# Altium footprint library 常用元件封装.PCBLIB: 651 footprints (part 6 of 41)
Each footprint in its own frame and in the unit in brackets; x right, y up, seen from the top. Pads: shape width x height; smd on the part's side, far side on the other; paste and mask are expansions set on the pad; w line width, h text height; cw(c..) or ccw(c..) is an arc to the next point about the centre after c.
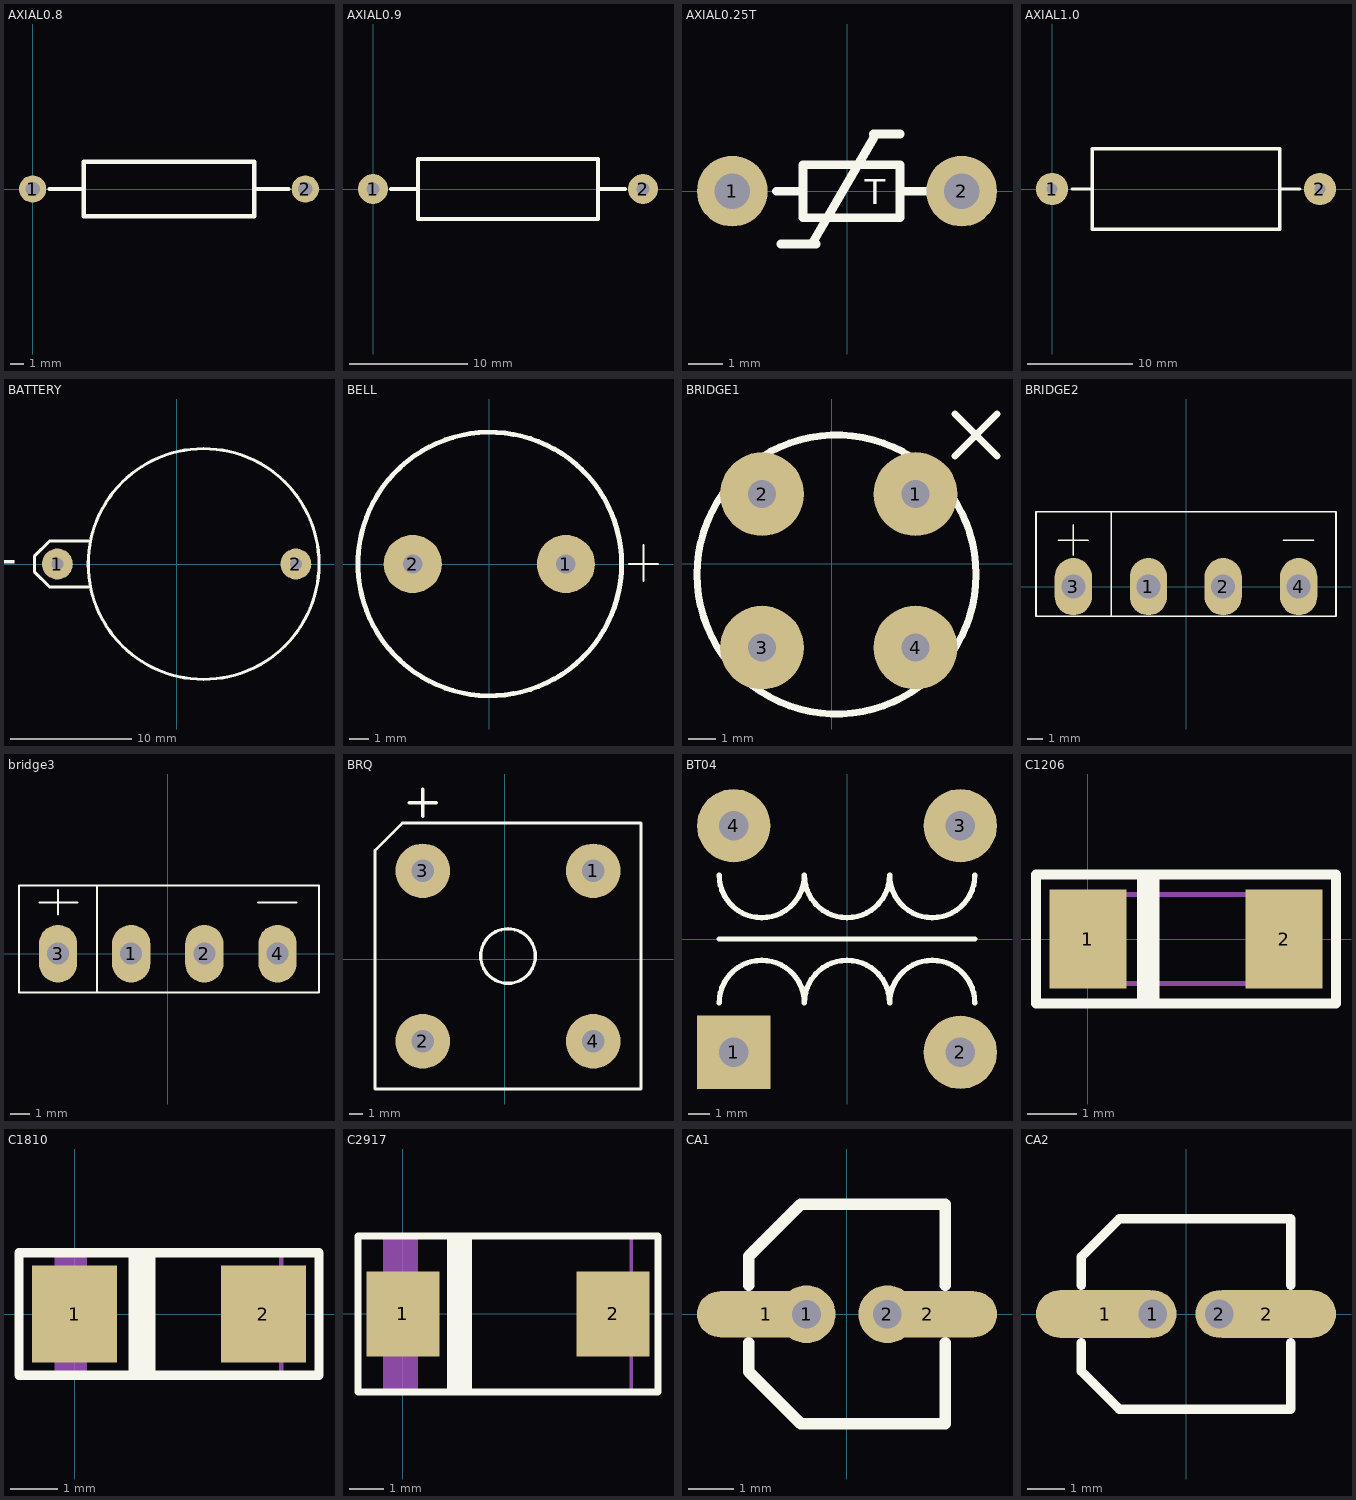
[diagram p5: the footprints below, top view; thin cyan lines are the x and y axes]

## AXIAL0.8 [mil] "20.32mm 3W 4W"
pads (2):
  round 80 hole 41.81: 1(0,0) 2(800,0)
TopOverlay:
  lines w12: 50,0 150,0 ; 650,0 750,0 ; 150,-80 650,-80 650,80 150,80 150,-80

## AXIAL0.9 [mil] "22.86mm"
pads (2):
  round 100 hole 41.81: 1(0,0) 2(900,0)
TopOverlay:
  lines w12: 60,0 150,0 ; 750,0 840,0 ; 150,-100 150,100 750,100 750,-100 150,-100

## AXIAL0.25T [mil]
pads (2):
  round 80 hole 40: 1(-130,0) 2(130,0)
TopOverlay:
  lines w10: -80,0 -50,0 ; -75,-60 -35,-60 ; -40,-60 30,60 ; 30,65 60,65 ; 60,0 90,0 ; -50,-30 60,-30 60,30 -50,30 -50,-30
  text "T" at 20,-15 h28

## AXIAL1.0 [mil] "25.4mm"
pads (2):
  round 120 hole 41.81: 1(0,0) 2(1000,0)
TopOverlay:
  lines w12: 75,0 150,0 ; 850,0 925,0 ; 150,-150 150,150 850,150 850,-150 150,-150

## BATTERY [mil]
pads (2):
  round 100 hole 40: 1(-387.5,0) 2(387.5,0)
TopOverlay:
  circle w10: c87.5,0 r375
  lines w10: -287.5,-75 -412.5,-75 -462.5,-25 -462.5,25 -412.5,75 -287.5,75
  text "+" at -512.5,50 h100

## BELL [mil]
pads (2):
  round 120 hole 40: 1(158,0) 2(-158,0)
TopOverlay:
  circle w10: c1.11,0 r271.89
  lines w4: 288,0 313,0 ; 302,0 348,0 ; 318,-35 318,39

## BRIDGE1 [mil]
pads (4):
  round 120 hole 40: 1(120,100) 2(-100,100) 3(-100,-120) 4(120,-120)
TopOverlay:
  circle w10: c6.8,-15.2 r200
  lines w10: 176.8,154.8 236.8,214.8 ; 176.8,214.8 236.8,154.8

## BRIDGE2 [mil]
pads (4):
  oval 98x150 hole 63: 1(-98.5,0) 2(97.5,0) 3(-295.5,0) 4(295.5,0)
TopOverlay:
  lines w4: -334.5,122 -256.5,122 ; -295.5,83 -295.5,162 ; -196.5,-78 -196.5,197 ; 255.5,122 334.5,122 ; -393.5,-78 393.5,-78 393.5,197 -393.5,197 -393.5,-78

## bridge3 [mm]
pads (4):
  oval 2x3 hole 1.143: 1(-1.905,0) 2(1.905,0) 3(-5.715,0) 4(5.715,0)
TopOverlay:
  lines w0.102: -6.68,2.667 -4.699,2.667 ; -5.715,2.032 -5.715,3.302 ; -3.683,-2.032 -3.683,3.556 ; 4.699,2.667 6.706,2.667 ; -7.747,-2.032 -7.747,3.556 7.874,3.556 7.874,-2.032 -7.747,-2.032

## BRQ [mil]
pads (4):
  round 160 hole 65: 1(260,260) 2(-240,-240) 3(-240,260) 4(260,-240)
TopOverlay:
  circle w10: c10.04,10.04 r80
  lines w8: -380,-380 400,-380 400,400 -300,400 -380,320 -380,-380
  lines w10: -280,460 -200,460 ; -240,420 -240,500

## BT04 [mm]
pads (4):
  rect 3.5x3.5 hole 1.4: 1(-5.4,-5.4)
  round 3.5 hole 1.4: 2(5.4,-5.4) 3(5.4,5.4) 4(-5.4,5.4)
TopOverlay:
  lines w0.254: -6.096,-3.048 cw(c-4.064,-3.048) -2.032,-3.048 cw(c0,-3.048) 2.032,-3.048 cw(c4.064,-3.048) 6.096,-3.048 ; -6.096,0 6.096,0 ; -6.096,3.048 ccw(c-4.064,3.048) -2.032,3.048 ccw(c0,3.048) 2.032,3.048 ccw(c4.064,3.048) 6.096,3.048

## C1206 [mm] "贴片电解电容"
height 1.8
pads (2):
  rect 1.55x2 smd: 1(0,0) 2(3.95,0)
TopOverlay:
  lines w0.2: -1.043,-1.3 -1.043,1.3 -0.275,1.3 4.225,1.3 4.993,1.3 4.993,-1.3 ; -1.013,-1.3 -0.275,-1.3 4.225,-1.3 4.963,-1.3 ; 1.086,-1.3 1.086,1.3 ; 1.213,-1.3 1.213,1.3 ; 1.34,-1.3 1.34,1.3
Mechanical13:
  rectangle: 0.275,-0.9 0.732,0.9
  lines w0.1: 0.275,-0.9 3.675,-0.9 3.675,0.9 0.275,0.9 0.275,-0.9

## C1810 [mm] "贴片电解电容4.8mmX2.6mm"
height 1.9
pads (2):
  rect 1.8x2.05 smd: 1(0,0) 2(4,0)
TopOverlay:
  lines w0.2: 1.238,-1.173 1.238,1.3 ; 1.365,-1.3 1.365,1.3 ; 1.492,-1.3 1.492,1.3 ; 1.619,-1.3 1.619,1.3 ; -1.175,-1.3 -1.175,1.3 5.175,1.3 5.175,-1.3 -1.175,-1.3
Mechanical13:
  rectangle: -0.375,-1.3 0.264,1.3
  lines w0.1: -0.375,-1.3 4.375,-1.3 4.375,1.3 -0.375,1.3 -0.375,-1.3
3D body: height 1.9, standoff 0, extent -0.375,-1.3 4.375,1.3

## C2917 [mm] "贴片电解电容7.3mmX4.3mm"
height 3
pads (2):
  rect 2.1x2.45 smd: 1(0,0) 2(6.05,0)
TopOverlay:
  lines w0.2: 1.374,-2.25 1.374,2.25 ; 1.501,-2.25 1.501,2.25 ; 1.628,-2.25 1.628,2.25 ; 1.755,-2.25 1.755,2.25 ; 1.882,-2.25 1.882,2.25 ; -1.293,-2.25 -1.293,2.25 7.343,2.25 7.343,-2.25 -1.293,-2.25
Mechanical13:
  rectangle: -0.525,-2.25 0.43,2.25
  lines w0.1: -0.525,-2.25 6.575,-2.25 6.575,2.25 -0.525,2.25 -0.525,-2.25
3D body: height 3, standoff 0, extent -0.525,-2.25 6.575,2.25

## CA1 [mil] "直径4mm孔距1.778mm"
height 196.85
pads (4):
  oval 120x40 smd: 1(-69.96,0) 2(70,0)
  round 50 hole 25: 1(-35,0) 2(34.96,0)
TopOverlay:
  lines w10: -85,-24.79 -85,-49.79 -40,-94.79 85,-94.79 85,-24.79 ; -85,25.21 -85,50.21 -40,95.21 85,95.21 85,25.21

## CA2 [mil] "直径5mm孔距1.778mm"
height 216.54
pads (4):
  oval 145x50 smd: 1(-85,0) 2(85,0)
  round 50 hole 30: 1(-35,0) 2(35,0)
TopOverlay:
  lines w10: -110,-30 -110,-60 -70,-100 110,-100 110,-30 ; -110,30 -110,60 -70,100 110,100 110,30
